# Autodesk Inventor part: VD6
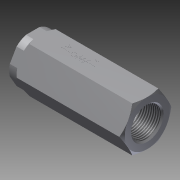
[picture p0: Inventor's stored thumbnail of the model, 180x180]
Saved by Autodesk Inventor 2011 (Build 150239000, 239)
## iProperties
Created: 2012-01
Part Number: VD6
Document SubType Name: Modeling
Designer: khramov
Density: 1 g/cm^3
Author: khramov
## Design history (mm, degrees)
derived "VD6_W1_30.ipt"
feature "Твердое тело1::VD6_W1_30.ipt" dims "d0" = 10
tag "Элемент создания маркировки1"
node "Твердое тело1"
